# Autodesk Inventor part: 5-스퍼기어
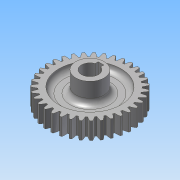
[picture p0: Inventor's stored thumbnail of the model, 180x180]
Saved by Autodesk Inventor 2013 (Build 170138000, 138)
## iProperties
Created: 2013-08
Part Number: 5-스퍼기어
Material: 강
Document SubType Name: Modeling
Designer: 한국산업디자인학원
Categories: <?xml version="1.0" encoding="UTF-16"?> <MemberInstance><Categories><FamilyTemplate><FamilyTemplateParameter ValueType="xs:double" Id="1" ObjectReferenceKey="da
Density: 1 g/cm^3
CustomPartVersion: 1
Author: 한국산업디자인학원
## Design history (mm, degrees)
sketch "Sketch1"
  geometry: C1 r 37 at (0, 0)
  constraints: 1 centre point
  dimensions: "d0" = 74 diameter of C1 (= da_da)
extrude "Extrusion1" new body sketch "Sketch1" distance "d1" = 15 (= da_b); taper "d2" = 0 deg
workplane "Work Plane2"
feature "피치 지름" dims "d4" = 10, "d5" = 0
workplane "Work Plane8"
workplane "Work Plane9"
feature "스퍼 기어" dims "da_b" = 15, "da_d" = 70, "da_aw" = 70, "da_da" = 74, "da_df" = 65, "da_dw" = 70, angle "da_beta" = 0 deg, "da_lefttooth" = 0, "da_righttooth" = 0
node "작업 평면11"
sketch "스케치3"
  geometry: C1 r 12.5 at (0, 0); 1 further point
  constraints: 1 centre point, 1 coincident
  dimensions: "d50" = 25 diameter of C1
extrude "돌출2" join sketch "스케치3" distance "d52" = 31; taper "d53" = 0 deg
sketch "스케치4"
  geometry: L1 (-2.5, 7.071)-(-2.5, 9.8); L2 (-2.5, 9.8)-(2.5, 9.8); L3 (2.5, 9.8)-(2.5, 7.071); C1 r 12.5 at (0, 0) reference; A1 r 7.5 centre (0, 0) between (-2.5, 7.071) and (2.5, 7.071)
  constraints: 6 end point, 2 parallel, 2 point on circle, 1 centre point, 1 coincident, 1 perpendicular, 1 vertical
  dimensions: "d54" = 15 diameter of A1; "d56" = 5 distance of L1.end L2.end; "d57" = 17.3 dimension on A1 L2
extrude "돌출3" cut sketch "스케치4" stored distance "d58" = 31; taper "d59" = 0 deg
sketch "스케치5"
  geometry: C1 r 12.5 at (0, 0) reference; C2 r 27.5 at (0, 0); C3 r 12.5 at (0, 0); A1 r 37 centre (0, 0) between (-5.788, 36.544) and (-7.422, 36.248) reference
  constraints: 2 centre point, 2 coincident, 1 concentric
  dimensions: "d60" = 55 diameter of C2
extrude "돌출4" cut sketch "스케치5" distance "d62" = 5; taper "d63" = 0 deg
sketch "스케치6"
  geometry: C1 r 12.5 at (0, 0) reference; C2 r 27.5 at (0, 0); C3 r 12.5 at (0, 0); A1 r 32.5 centre (0, 0) between (9.347, 31.127) and (7.941, 31.515) reference
  constraints: 2 centre point, 2 coincident, 1 concentric
  dimensions: "d64" = 55 diameter of C2
extrude "돌출5" cut sketch "스케치6" distance "d66" = 5; taper "d67" = 0 deg
fillet "모깎기1" dims "d68" = 5
body "Solid1"
sketch "Sketch2"
  geometry: C1 r 37 at (0, 0) reference; C2 r 35 at (0, 0)
  constraints: 1 centre point, 1 coincident
  dimensions: "d3" = 70 diameter of C2 (= da_dw)
body "Srf1"
other parameters: "d17" = 0, "d34" = 0.8976 (computed from da_z), "d39" = 0, "d41" = 0, "d47" = 0, "d48" = 0, "d49" = -3
